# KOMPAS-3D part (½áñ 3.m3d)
File: created 10.02.2016 11:24:24, last saved 22.07.2016 16:33:15.
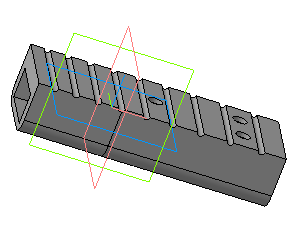
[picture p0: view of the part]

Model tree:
1. Эскиз:1
2. Операция выдавливания:1
     Расстояние 1 = 8
3. Эскиз:2
4. Операция выдавливания:2
     Расстояние 1 = 15.5
5. Вырезать элемент выдавливания:1
     Расстояние 1 = 320
6. Скругление:1
     Радиус = 7
7. Эскиз:3
8. Вырезать элемент выдавливания:2
     Расстояние 1 = 20
9. Эскиз:4
10. Вырезать элемент выдавливания:3
     Расстояние 2 = 40; Расстояние 1 = 65
11. Эскиз:5
12. Вырезать элемент выдавливания:4
     Расстояние 2 = 40; Расстояние 1 = 2
13. Эскиз:7
14. Вырезать элемент выдавливания:5
     Расстояние 1 = 40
